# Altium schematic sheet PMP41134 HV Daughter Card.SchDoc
size 431 x 279 mm; PageSetup: Record=PageOptions¦CenterHorizontal=True¦CenterVertical=True¦PrintScale=1.00¦XCorrection=1.00¦YCorrection=1.00¦PrintKind=0¦BorderSize=5000000¦LeftOffset=0¦BottomOffset=0¦Orientation=2¦PaperLength=1000¦PaperWidth=1000¦Scale=100¦PaperSource=15¦PrintQuality=600¦MediaType=1¦DitherType=10¦PaperKind=Letter¦PrintScaleMode=1
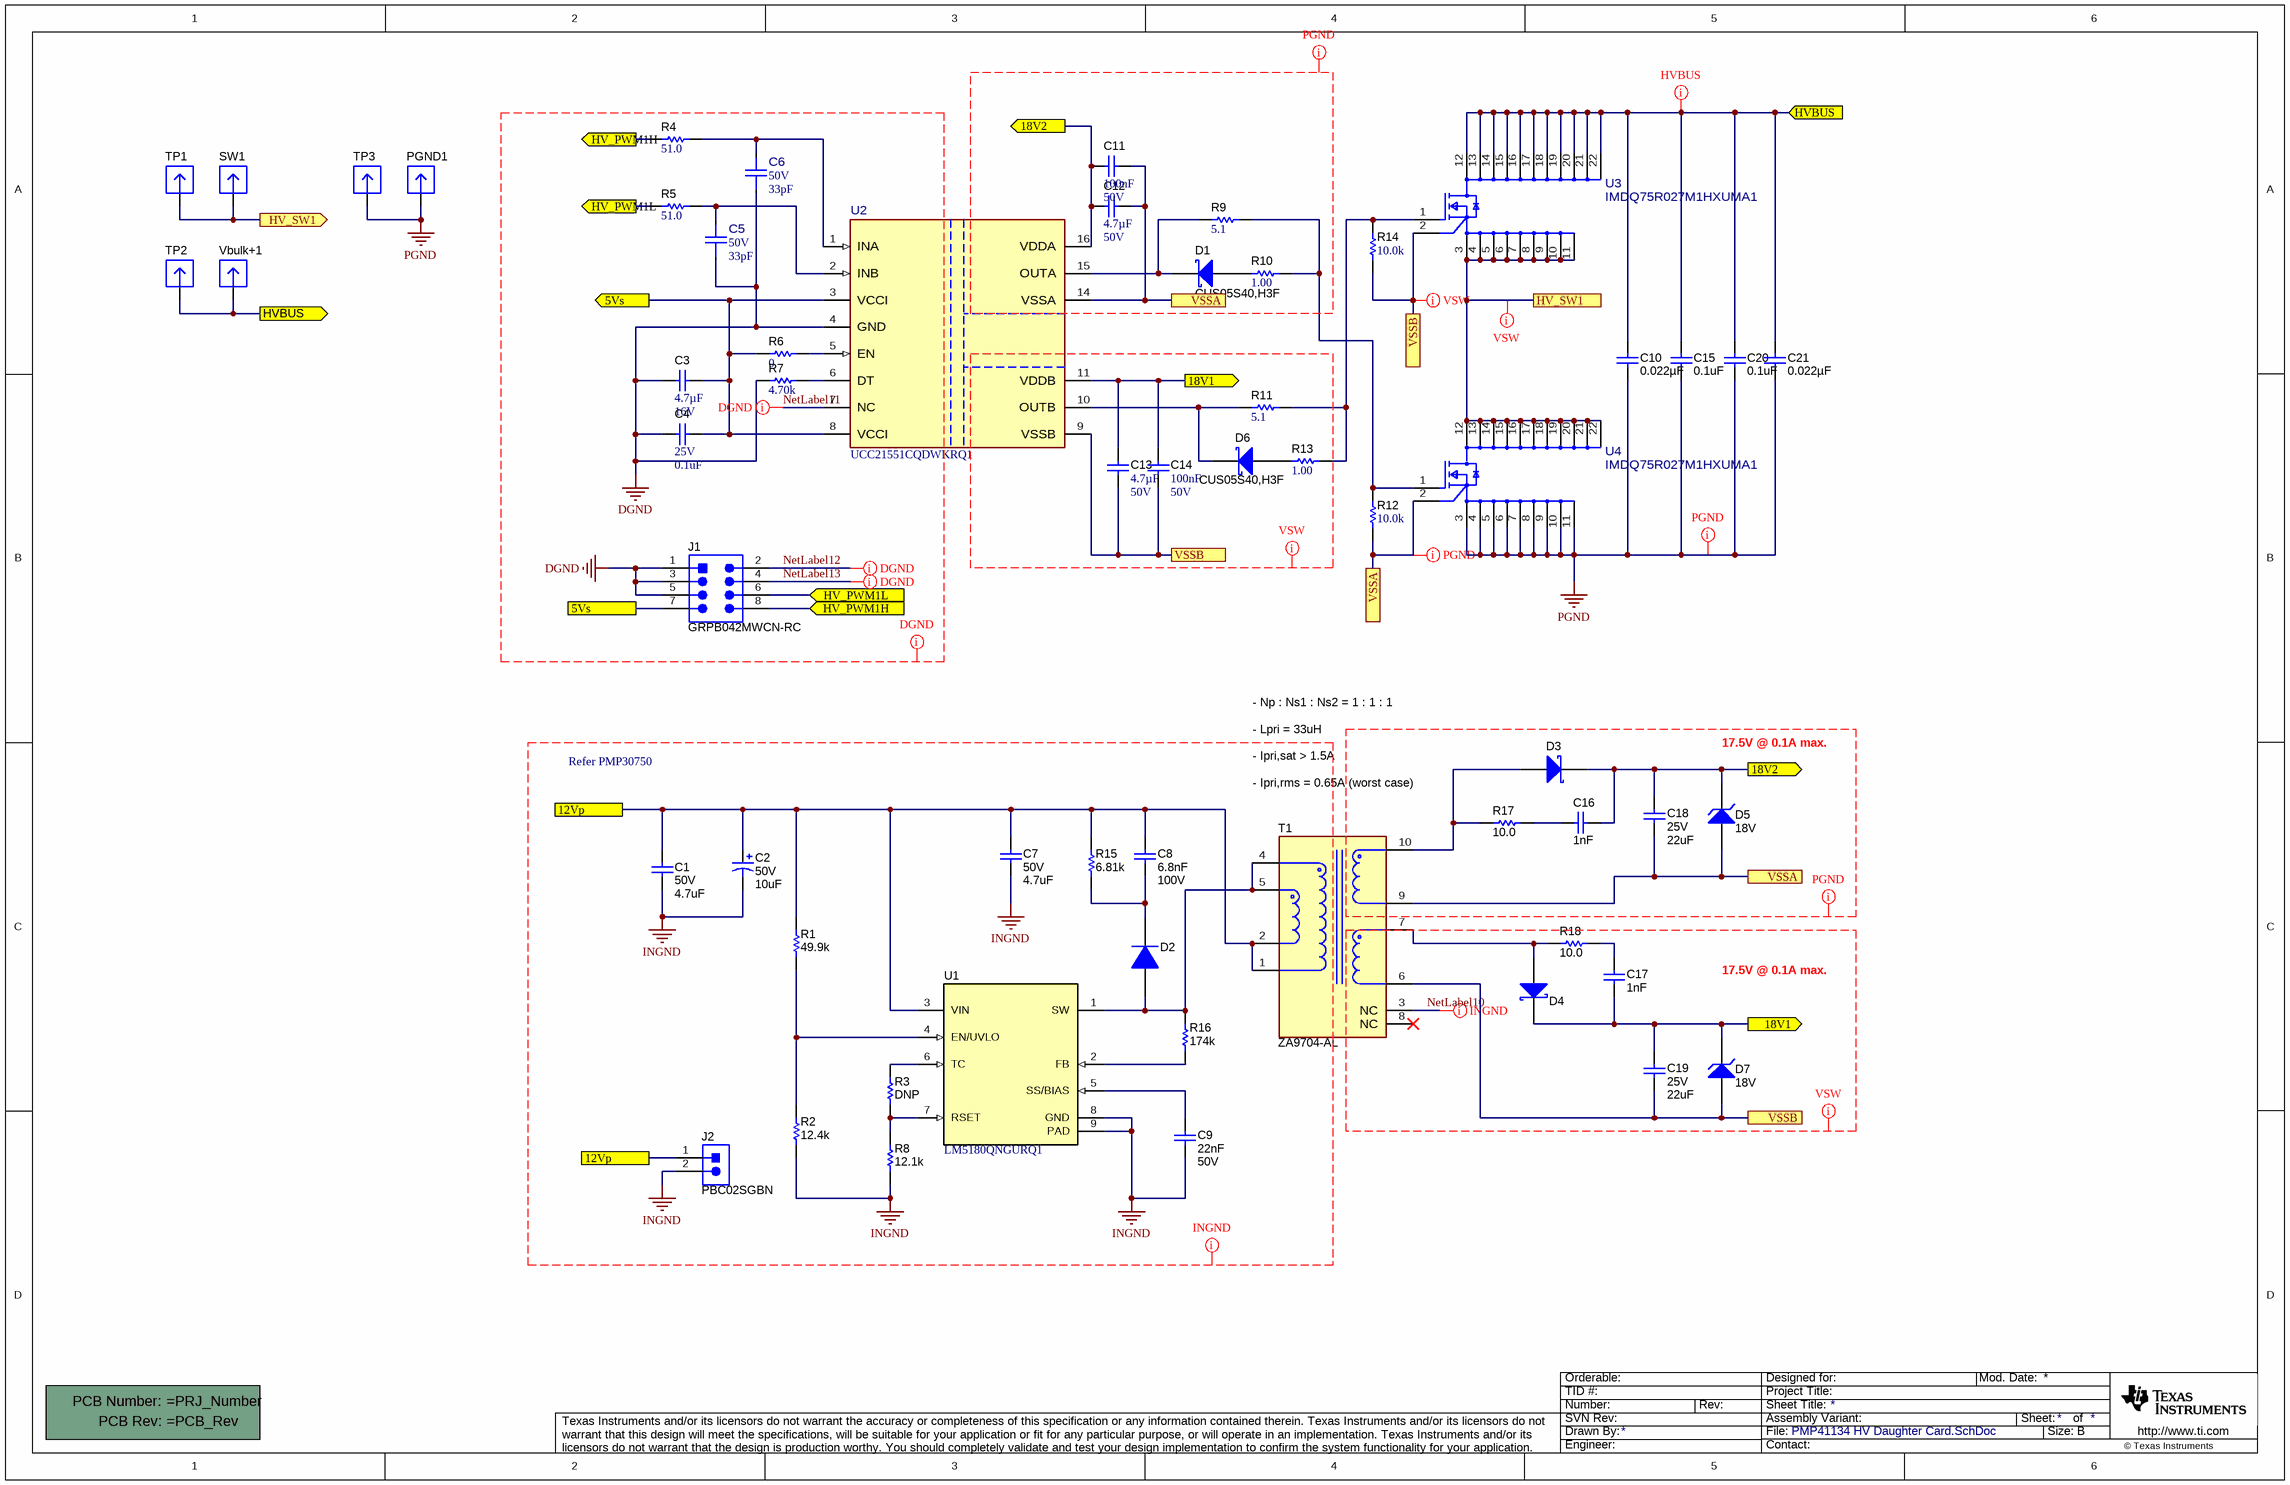
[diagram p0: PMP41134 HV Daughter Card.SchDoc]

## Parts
!PCB1  Printed Circuit Board  (value not drawn)  (mechanical)
C1  VDC_V: 50V  ValueDisplayed: 4.7uF  [1206_180]  (hidden comment: GRM31CR71H475KA12L)
C2  VDC_V: 50V  ValueDisplayed: 10uF  [SM_RADIAL_D]  (hidden comment: EEE-FK1H100P)
C3  Cap_F: 4.7µF  VDC_V: 16V  [0603]  (hidden comment: GRM188Z71C475KE21D)
C4  VDC_V: 25V  ValueDisplayed: 0.1uF  [0402]  (hidden comment: GRM155R71E104KE14D)
C5  VDC_V: 50V  ValueDisplayed: 33pF  [FP-CGA3E2C0G1H330J080AA_0603-MFG]  (hidden comment: CGA3E2C0G1H330J080AA)
C6  VDC_V: 50V  ValueDisplayed: 33pF  [FP-CGA3E2C0G1H330J080AA_0603-MFG]  (hidden comment: CGA3E2C0G1H330J080AA)
C7  VDC_V: 50V  ValueDisplayed: 4.7uF  [1206_180]  (hidden comment: GRM31CR71H475KA12L)
C8  Cap_F: 6.8nF  VDC_V: 100V  [0603]  (hidden comment: GRM188R72A682KA01D)
C9  Cap_F: 22nF  VDC_V: 50V  [0603]  (hidden comment: GRM188R71H223KA01D)
C10  ValueDisplayed: 0.022µF  [1206_190]  (hidden comment: C1206C223KDRACTU)
C11  Cap_F: 100nF  VDC_V: 50V  [0603]  (hidden comment: 885012206095)
C12  ValueDisplayed: 4.7µF  VDC_V: 50V  [1206_190]  (hidden comment: CGA5L3X7R1H475K160AE)
C13  ValueDisplayed: 4.7µF  VDC_V: 50V  [1206_190]  (hidden comment: CGA5L3X7R1H475K160AE)
C14  Cap_F: 100nF  VDC_V: 50V  [0603]  (hidden comment: 885012206095)
C15  ValueDisplayed: 0.1uF  [1812_254]  (hidden comment: C1812W104KDRACTU)
C16  Cap_F: 1nF  [0603]  (hidden comment: GRM188R71H102KA01D)
C17  Cap_F: 1nF  [0603]  (hidden comment: GRM188R71H102KA01D)
C18  VDC_V: 25V  ValueDisplayed: 22uF  [1210_270]  (hidden comment: TMK325B7226MM-PR)
C19  VDC_V: 25V  ValueDisplayed: 22uF  [1210_270]  (hidden comment: TMK325B7226MM-PR)
C20  ValueDisplayed: 0.1uF  [1812_254]  (hidden comment: C1812W104KDRACTU)
C21  ValueDisplayed: 0.022µF  [1206_190]  (hidden comment: C1206C223KDRACTU)
D1  CUS05S40,H3F  [SOD-323]
D2  BAS16D-E3-08  [SOD-123]  (value not drawn)
D3  PMEG6010CEH,115  [SOD-123]  (value not drawn)
D4  PMEG6010CEH,115  [SOD-123]  (value not drawn)
D5  value 18V  [SOD-123]  (hidden comment: MMSZ5248B-7-F)
D6  CUS05S40,H3F  [SOD-323]
D7  value 18V  [SOD-123]  (hidden comment: MMSZ5248B-7-F)
J1  GRPB042MWCN-RC  [Sullins_GRPB042MWCN]
J2  PBC02SGBN  [Sullins_PxC02SGBN]
PGND1  3621-0-32-15-00-00-08-0  [Mill-Max_3621-0-32-xx-00-00-08-0]  (value not drawn)
R1  ValueDisplayed: 49.9k  [0603]  (hidden comment: CRCW060349K9FKEA)
R2  ValueDisplayed: 12.4k  [0603]  (hidden comment: CRCW060312K4FKEA)
R3  ValueDisplayed: DNP  [0603]  (hidden comment: CRCW0603432KFKEA)
R4  ValueDisplayed: 51.0  [0603]  (hidden comment: RC0603FR-0751RL)
R5  ValueDisplayed: 51.0  [0603]  (hidden comment: RC0603FR-0751RL)
R6  ValueDisplayed: 0  [0402]  (hidden comment: RC0402JR-070RL)
R7  ValueDisplayed: 4.70k  [0402]  (hidden comment: CRG0402F4K7)
R8  ValueDisplayed: 12.1k  [0603]  (hidden comment: CRCW060312K1FKEA)
R9  ValueDisplayed: 5.1  [0603]  (hidden comment: CRCW06035R10JNEA)
R10  ValueDisplayed: 1.00  [0603]  (hidden comment: RC0603FR-071RL)
R11  ValueDisplayed: 5.1  [0603]  (hidden comment: CRCW06035R10JNEA)
R12  ValueDisplayed: 10.0k  [0402]  (hidden comment: ERJ-2RKF1002X)
R13  ValueDisplayed: 1.00  [0603]  (hidden comment: RC0603FR-071RL)
R14  ValueDisplayed: 10.0k  [0402]  (hidden comment: ERJ-2RKF1002X)
R15  ValueDisplayed: 6.81k  [0603]  (hidden comment: CRCW06036K81FKEA)
R16  ValueDisplayed: 174k  [0603]  (hidden comment: CRCW0603174KFKEA)
R17  ValueDisplayed: 10.0  [0603]  (hidden comment: CRCW060310R0FKEAHP)
R18  ValueDisplayed: 10.0  [0603]  (hidden comment: CRCW060310R0FKEAHP)
SW1  3621-0-32-15-00-00-08-0  [Mill-Max_3621-0-32-xx-00-00-08-0]  (value not drawn)
T1  ZA9704-AL  [FP-ZA9704-AL_SMD10-MFG]
TP1  3621-0-32-15-00-00-08-0  [Mill-Max_3621-0-32-xx-00-00-08-0]  (value not drawn)
TP2  3621-0-32-15-00-00-08-0  [Mill-Max_3621-0-32-xx-00-00-08-0]  (value not drawn)
TP3  3621-0-32-15-00-00-08-0  [Mill-Max_3621-0-32-xx-00-00-08-0]  (value not drawn)
U1  LM5180QNGURQ1  [NGU0008C]
U2  UCC21551CQDWKRQ1  [DWK0014A-MFG]
U3  IMDQ75R027M1HXUMA1  [FP-IMDQ75R027M1HXUMA1_HDSOP22-MFG]
U4  IMDQ75R027M1HXUMA1  [FP-IMDQ75R027M1HXUMA1_HDSOP22-MFG]
Vbulk+1  3621-0-32-15-00-00-08-0  [Mill-Max_3621-0-32-xx-00-00-08-0]  (value not drawn)

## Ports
5Vs, 5Vs (out), 12Vp, 18V1 (out), 18V2 (out), HV_PWM1H (in), HV_PWM1H (out), HV_PWM1L (in), HV_PWM1L (out), HV_SW1, HV_SW1 (out), HVBUS (in), HVBUS (out), VSSA, VSSB

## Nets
DGND: C3.1 C4.2 C5.1 C6.1 J1.1 J1.3 J1.5 R7.2 U2.4(GND)
INGND: C1.2 C2.2(-) C7.2 C9.2 J2.2 R2.1 R8.1 U1.8(GND) U1.9(PAD)
PGND: C10.2 C15.2 C20.2 C21.2 PGND1.1 TP3.1 U4.3(Power_Source) U4.4(Power_Source) U4.5(Power_Source) U4.6(Power_Source) U4.7(Power_Source) U4.8(Power_Source) U4.9(Power_Source) U4.10(Power_Source) U4.11(Power_Source)
5Vs: C3.2 C4.1 J1.7 R6.1 U2.3(VCCI) U2.8(VCCI) ; port 5Vs
12Vp: C1.1 C2.1(+) C7.1 C8.1 J2.1 R1.2 R15.2 T1.1 T1.2 U1.3(VIN) ; port 12Vp
18V1: C13.1 C14.1 C17.2 C19.1 D4.1(K) D7.1(K) U2.11(VDDB) ; port 18V1
18V2: C11.1 C12.1 C16.1 C18.1 D3.1(K) D5.1(K) U2.16(VDDA) ; port 18V2
HV_PWM1H: J1.8 R4.1 ; port HV_PWM1H
HV_PWM1L: J1.6 R5.1 ; port HV_PWM1L
HV_SW1: SW1.1 TP1.1 U3.3(Power_Source) U3.4(Power_Source) U3.5(Power_Source) U3.6(Power_Source) U3.7(Power_Source) U3.8(Power_Source) U3.9(Power_Source) U3.10(Power_Source) U3.11(Power_Source) U4.12(Drain) U4.13(Drain) U4.14(Drain) U4.15(Drain) U4.16(Drain) U4.17(Drain) U4.18(Drain) U4.19(Drain) U4.20(Drain) U4.21(Drain) U4.22(Drain) ; port HV_SW1
HVBUS: C10.1 C15.1 C20.1 C21.1 TP2.1 U3.12(Drain) U3.13(Drain) U3.14(Drain) U3.15(Drain) U3.16(Drain) U3.17(Drain) U3.18(Drain) U3.19(Drain) U3.20(Drain) U3.21(Drain) U3.22(Drain) Vbulk+1.1 ; port HVBUS
NetLabel10: T1.3(NC)
NetLabel11: U2.7(NC)
NetLabel12: J1.2
NetLabel13: J1.4
VSSA: C11.2 C12.2 C18.2 D5.2(A) R12.1 T1.9 U2.14(VSSA) U4.2(Driver_Source) ; port VSSA
VSSB: C13.2 C14.2 C19.2 D7.2(A) R14.1 T1.6 U2.9(VSSB) U3.2(Driver_Source) ; port VSSB
NetC5_2: C5.2 R5.2 U2.2(INB)
NetC6_2: C6.2 R4.2 U2.1(INA)
NetC8_2: C8.2 D2.1(K) R15.1
NetC9_1: C9.1 U1.5(SS/BIAS)
NetC16_2: C16.2 R17.2
NetC17_1: C17.1 R18.2
NetD1_1: D1.1(K) R9.1 U2.15(OUTA)
NetD1_2: D1.2(A) R10.1
NetD2_2: D2.2(A) R16.2 T1.4 T1.5 U1.1(SW)
NetD3_2: D3.2(A) R17.1 T1.10
NetD4_2: D4.2(A) R18.1 T1.7
NetD6_1: D6.1(K) R11.1 U2.10(OUTB)
NetD6_2: D6.2(A) R13.1
NetR1_1: R1.1 R2.2 U1.4(EN/UVLO)
NetR3_1: R3.1 R8.2 U1.7(RSET)
NetR3_2: R3.2 U1.6(TC)
NetR6_2: R6.2 U2.5(EN)
NetR7_1: R7.1 U2.6(DT)
NetR9_2: R9.2 R10.2 R12.2 U4.1(Gate)
NetR11_2: R11.2 R13.2 R14.2 U3.1(Gate)
NetR16_1: R16.1 U1.2(FB)

Not connected (* = marked no-connect by the designer): T1 8(NC)*

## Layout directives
net class INGND: INGND, NetLabel10
net class HVBUS: HVBUS
net class PGND: (no net found under the mark), PGND, VSSA
net class VSW: (no net found under the mark), HV_SW1, NetLabel10, VSSB
net class DGND: DGND, NetLabel11, NetLabel12, NetLabel13

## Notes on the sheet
- - Np : Ns1 : Ns2 = 1 : 1 : 1
- Refer PMP30750
- - Lpri = 33uH
- - Ipri,sat > 1.5A
- 17.5V @ 0.1A max.
- - Ipri,rms = 0.65A (worst case)

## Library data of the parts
!PCB1 = CMP-0003618-2: Manufacturer: Any
C1 C7 = CMP-0008969-2: CAP, CERM, 4.7 uF, 50 V, +/- 10%, X7R, 1206; Manufacturer: MuRata; TaMin_C: -55°C; Polarized: N; SizeAreaWB_mm2: 10.92; Value1: Unknown; U/M: EA; Value: 4.7uF; TaMax_C: 125°C; SizeZ_mm: 1.8; SizeX_mm: 3.2; SizeY_mm: 1.6; Cap_Case: 2220; SizeArea_mm2: 5.12; Cap_F: 4.7µF; AEC Category: Q200
C2 = CMP-0011175-2: CAP, AL, 10 uF, 50 V, +/- 20%, 0.88 ohm, AEC-Q200 Grade 2, SMD; Manufacturer: Panasonic; TaMin_C: -55°C; ESR_ohm: 0.88; Polarized: Y; SizeAreaWB_mm2: 84.28; U/M: EA; Value: 10uF; TaMax_C: 105°C; SizeZ_mm: 5.4; SizeX_mm: 7.8; SizeY_mm: 6.6; Cap_Case: D; SizeArea_mm2: 51.48; CompType: Capacitor; Cap_F: 10µF; IRMS_A: 165mA; AEC Grade: 2; AEC Category: Q200
C3 = CMP-0064936-4: CAP, CERM, 4.7 uF, 16 V,+/- 10%, X7R, 0603; Manufacturer: MuRata; TaMin_C: -55°C; Polarized: N; SizeAreaWB_mm2: 4.68; Value1: Unknown; U/M: EA; Value: 4.7uF; TaMax_C: 125°C; SizeZ_mm: 1; SizeX_mm: 1.6; SizeY_mm: 0.8; SizeArea_mm2: 1.28; AEC Category: Q200
C4 = CMP-0006659-2: CAP, CERM, 0.1 uF, 25 V, +/- 10%, X7R, 0402; Manufacturer: MuRata; TaMin_C: -55°C; Polarized: N; SizeAreaWB_mm2: 3; Value1: Unknown; U/M: EA; Value: 0.1uF; TaMax_C: 125°C; SizeZ_mm: 0.6; SizeX_mm: 1; SizeY_mm: 0.5; Cap_F: 100nF; AEC Category: Q200
C5 C6 = CMP-0095622-1: Cap Ceramic 33pF 50V C0G 5% Pad SMD 0603 +125°C Automotive T/R; Manufacturer: TDK; SizeZ_mm: 1.1mm; AEC Grade: Grade 1; Tolerance_%: 0.05%; AEC Qualified: Yes; TempCo: 30ppm/°C
C8 = CMP-0007487-4: CAP, CERM, 6800 pF, 100 V, +/- 10%, X7R, 0603; Manufacturer: MuRata; TaMin_C: -55°C; Polarized: N; SizeAreaWB_mm2: 4.68; Value1: Unknown; U/M: EA; Value: 6800pF; TaMax_C: 125°C; SizeZ_mm: 1; SizeX_mm: 1.6; SizeY_mm: 0.8; SizeArea_mm2: 1.28; AEC Category: Q200
C9 = CMP-0007444-4: CAP, CERM, 0.022 uF, 50 V, +/- 10%, X7R, 0603; Manufacturer: MuRata; TaMin_C: -55°C; Polarized: N; SizeAreaWB_mm2: 4.68; Value1: Unknown; U/M: EA; TaMax_C: 125°C; SizeZ_mm: 1; SizeX_mm: 1.6; SizeY_mm: 0.8; SizeArea_mm2: 1.28; AEC Category: Q200
C10 C21 = CMP-0084048-1: CAP, CERM, 0.022 µF, 1000 V,+/- 10%, X7R, AEC-Q200 Grade 1, 1206; Manufacturer: Kemet; Polarized: N; CompType: Capacitor; Value: 0.022uF; U/M: EA; Cap_F: 22nF; VDC_V: 1kV; Value2: 1000V; TaMin_C: -55°C; TaMax_C: 125°C; Cap_Case: 1206; SizeArea_mm2: 5.12; SizeAreaWB_mm2: 10.92; SizeX_mm: 3.2; SizeY_mm: 1.6; SizeZ_mm: 1.9; AEC Category: Q200; AEC Qualified: Y; AEC Grade: 1
C11 C14 = CMP-0006837-4: CAP, CERM, 0.1 uF, 50 V, +/- 10%, X7R, 0603; Manufacturer: Wurth Elektronik; TaMin_C: -55°C; Polarized: N; SizeAreaWB_mm2: 4.68; Value1: Unknown; U/M: EA; Value: 0.1uF; TaMax_C: 125°C; SizeZ_mm: 1; SizeX_mm: 1.6; SizeY_mm: 0.8; SizeArea_mm2: 1.28; AEC Category: Q200
C12 C13 = CMP-0085349-1: CAP, CERM, 4.7 µF, 50 V,+/- 10%, X7R, AEC-Q200 Grade 1, 1206; Manufacturer: TDK; Cap_Case: 1206; AEC Category: Q200; SizeY_mm: 1.6; TaMin_C: -55°C; TaMax_C: 125°C; U/M: EA; AEC Qualified: Y; SizeAreaWB_mm2: 10.92; AEC Grade: 1; SizeZ_mm: 1.9; SizeArea_mm2: 5.12; Value: 4.7uF; Polarized: N; SizeX_mm: 3.2
C15 C20 = CMP-0009326-2: CAP, CERM, 0.1 uF, 1000 V, +/- 10%, X7R, 1812; Manufacturer: Kemet; Polarized: N; Value: 0.1uF; U/M: EA; Cap_F: 100nF; Value1: Unknown; VDC_V: 1kV; Value2: 1000V; TaMin_C: -55°C; TaMax_C: 125°C; Cap_Case: 1812; AEC Category: Q200; SizeArea_mm2: 14.4; SizeAreaWB_mm2: 23.1; SizeX_mm: 4.5; SizeY_mm: 3.2; SizeZ_mm: 2.54
C16 C17 = CMP-0007432-5: CAP, CERM, 1000 pF, 50 V, +/- 10%, X7R, 0603; Manufacturer: MuRata; TaMin_C: -55°C; Polarized: N; SizeAreaWB_mm2: 4.68; Value1: Unknown; U/M: EA; Value: 1000pF; TaMax_C: 125°C; SizeZ_mm: 1; SizeX_mm: 1.6; SizeY_mm: 0.8; Value2: 50V; SizeArea_mm2: 1.28; AEC Category: Q200
C18 C19 = CMP-0009255-2: CAP, CERM, 22 uF, 25 V, +/- 10%, X7R, AEC-Q200 Grade 1, 1210; Manufacturer: Taiyo Yuden; TaMin_C: -55°C; Polarized: N; SizeAreaWB_mm2: 14.7; Value1: Unknown; U/M: EA; Value: 22uF; TaMax_C: 125°C; SizeZ_mm: 2.7; SizeX_mm: 3.2; SizeY_mm: 2.5; Cap_Case: 1210; SizeArea_mm2: 8; AEC Qualified: Y; Cap_F: 22µF; AEC Grade: 1; AEC Category: Q200
D1 D6 = CMP-0028748-2: Diode, Schottky, 40 V, 0.5 A, SOD-323; Manufacturer: Toshiba; TJmax_C: 125°C; Value: 40V; SizeZ_mm: 1; Value1: 0.5A; Value2: 0.6V; Io_A: 500mA; AEC Qualified: N; SizeAreaWB_mm2: 8.695; SizeY_mm: 1.35; SizeArea_mm2: 3.645; SizeX_mm: 2.7; AEC Category: Q101; Vf_V: 600mV; Green_Lifecycle: Not Set; Green_REACh: Incomplete
D2 = CMP-0080761-1: Diode, Switching, 100 V, 0.25 A, AEC-Q101, SOD-123; Manufacturer: Vishay-Semiconductor; Io_A: 250mA; SizeAreaWB_mm2: 13.095; Vr_V: 100V; Value1: 0.25A; TJmax_C: 150°C; Value: 100V; SizeZ_mm: 1.35; SizeX_mm: 3.85; SizeY_mm: 1.7; Vf_V: 1.25V; SizeArea_mm2: 6.545; AEC Qualified: Y; AEC Category: Q101
D3 D4 = CMP-0028377-2: Diode, Schottky, 60 V, 1 A, SOD-123F; Manufacturer: Nexperia; Value1: 1A; Value2: 0.57V; TJmax_C: 150°C; Green_REACh: Incomplete; Vr_V: 60V; SizeY_mm: 1.6; Vf_V: 570mV; SizeArea_mm2: 5.6; AEC Category: Q101; SizeZ_mm: 1.1; SizeX_mm: 3.5; Value: 60V; Green_Lifecycle: Not Set; SizeAreaWB_mm2: 11.7
D5 D7 = CMP-0005755-1: Diode, Zener, 18 V, 500 mW, SOD-123; Manufacturer: Diodes Inc.; Power_W: 500mW; SizeAreaWB_mm2: 13.095; Value1: 0.5W; RJA_CperW: 350; U/M: EA; SizeZ_mm: 1.35; SizeX_mm: 3.85; SizeY_mm: 1.7; SizeArea_mm2: 6.545; AEC Category: Q101
J1 = CMP-0086278-1: Header, 1.27mm, 4x2, Gold, R/A, TH; Manufacturer: Sullins Connector Solutions; Current_A: 1A; Shrouded: N; Pitch_mm: 1.27; Voltage_V: 500V; Gender: Male; Row_Count: 2
J2 = CMP-0054714-1: Header, 2.54 mm, 2x1, Gold, R/A, TH; Manufacturer: Sullins Connector Solutions; CNHeader: FALSE; Current_A: 3A; Shrouded: N; Gender: Male; Voltage_V: 1.8kV; Row_Count: 1; Pitch_mm: 2.54; Cert_UL: Y
PGND1 SW1 TP1-TP3 Vbulk+1 = CMP-0082316-1: Manufacturer: Mill-Max; CompType: PCB Pin; ContactFinish: Gold; Gender: Male; Row_Count: 1
R1 = CMP-0022447-4: RES, 49.9 k, 1%, 0.1 W, AEC-Q200 Grade 0, 0603; Manufacturer: Vishay-Dale; Power_W: 100mW; TempCo: 100 ppm/C; Value_Code: 49k9; Value: 49.9k; EIA_Code: E96; SizeX_mm: 1.6; SizeY_mm: 0.8; SizeZ_mm: 1; Value2: 0.1W; SizeArea_mm2: 1.28; AEC Qualified: Y; VDC_V: 75V; AEC Category: Q200; AEC Grade: 0
R2 = CMP-0022031-4: RES, 12.4 k, 1%, 0.1 W, AEC-Q200 Grade 0, 0603; Manufacturer: Vishay-Dale; Power_W: 100mW; TempCo: 100 ppm/C; Value_Code: 12k4; Value: 12.4k; EIA_Code: E96; SizeX_mm: 1.6; SizeY_mm: 0.8; SizeZ_mm: 1; Value2: 0.1W; SizeArea_mm2: 1.28; AEC Qualified: Y; VDC_V: 75V; AEC Category: Q200; AEC Grade: 0
R3 = CMP-0022420-4: RES, 432 k, 1%, 0.1 W, AEC-Q200 Grade 0, 0603; Manufacturer: Vishay-Dale; Power_W: 100mW; TempCo: 100 ppm/C; Value_Code: 432k; Value: 432k; EIA_Code: E96; SizeX_mm: 1.6; SizeY_mm: 0.8; SizeZ_mm: 1; Value2: 0.1W; SizeArea_mm2: 1.28; AEC Qualified: Y; VDC_V: 75V; AEC Category: Q200; AEC Grade: 0
R4 R5 = CMP-0023169-5: RES, 51.0, 1%, 0.1 W, 0603; Manufacturer: Yageo; Power_W: 100mW; TempCo: 100 ppm/C; Value_Code: 51R0; Value: 51.0; Res_ohm: 51; SizeX_mm: 1.6; SizeY_mm: 0.8; SizeZ_mm: 1; Value2: 0.1W; SizeArea_mm2: 1.28; AEC Qualified: N; VDC_V: 75V; AEC Category: Q200; SizeAreaWB_mm2: 4.68
R6 = CMP-0027004-2: RES, 0, 5%, 0.063 W, 0402; Manufacturer: Yageo America; Power_W: 63mW; TempCo: 200 ppm/C; Value_Code: 0000; U/M: EA; Value: 0; EIA_Code: E24; SizeX_mm: 1; SizeY_mm: 0.5; SizeZ_mm: 0.6; Value2: 0.063W; VDC_V: 50V; AEC Category: Q200
R7 = CMP-0026631-1: RES, 4.70 k, 1%, 0.063 W, 0402; Manufacturer: TE Connectivity; Power_W: 63mW; TempCo: 100 ppm/C; Value_Code: 4k70; U/M: EA; Value: 4.70k; Res_ohm: 4.7k; SizeX_mm: 1; SizeY_mm: 0.5; SizeZ_mm: 0.6; Value2: 0.063W; AEC Qualified: N; AEC Category: Q200
R8 = CMP-0022030-4: RES, 12.1 k, 1%, 0.1 W, AEC-Q200 Grade 0, 0603; Manufacturer: Vishay-Dale; Power_W: 100mW; TempCo: 100 ppm/C; Value_Code: 12k1; Value: 12.1k; EIA_Code: E96; SizeX_mm: 1.6; SizeY_mm: 0.8; SizeZ_mm: 1; Value2: 0.1W; SizeArea_mm2: 1.28; AEC Qualified: Y; VDC_V: 75V; AEC Category: Q200; AEC Grade: 0
R9 R11 = CMP-0025834-4: RES, 5.1, 5%, 0.1 W, AEC-Q200 Grade 0, 0603; Manufacturer: Vishay-Dale; Power_W: 100mW; TempCo: 200 ppm/C; Value_Code: 5R10; Value: 5.1; EIA_Code: E24; SizeX_mm: 1.6; SizeY_mm: 0.8; SizeZ_mm: 1; Value2: 0.1W; SizeArea_mm2: 1.28; AEC Qualified: Y; VDC_V: 75V; AEC Category: Q200; AEC Grade: 0
R10 R13 = CMP-0022900-4: RES, 1.00, 1%, 0.1 W, 0603; Manufacturer: Yageo; Power_W: 100mW; TempCo: 200 ppm/C; Value_Code: 1R00; Value: 1.00; EIA_Code: E96; Res_ohm: 1; SizeX_mm: 1.6; SizeY_mm: 0.8; Value2: 0.1W; SizeArea_mm2: 1.28; AEC Qualified: N; VDC_V: 75V; AEC Category: Q200; SizeAreaWB_mm2: 4.68
R12 R14 = CMP-0026658-1: RES, 10.0 k, 1%, 0.1 W, 0402; Manufacturer: Panasonic; Power_W: 100mW; TempCo: 100 ppm/C; Value_Code: 10k0; U/M: EA; Value: 10.0k; EIA_Code: E96; Res_ohm: 10k; SizeX_mm: 1; SizeY_mm: 0.5; SizeZ_mm: 0.6; Value2: 0.1W; VDC_V: 50V; AEC Category: Q200
R15 = CMP-0022563-4: RES, 6.81 k, 1%, 0.1 W, AEC-Q200 Grade 0, 0603; Manufacturer: Vishay-Dale; Power_W: 100mW; TempCo: 100 ppm/C; Value_Code: 6k81; Value: 6.81k; EIA_Code: E96; SizeX_mm: 1.6; SizeY_mm: 0.8; SizeZ_mm: 1; Value2: 0.1W; SizeArea_mm2: 1.28; AEC Qualified: Y; VDC_V: 75V; AEC Category: Q200; AEC Grade: 0
R16 = CMP-0022085-4: RES, 174 k, 1%, 0.1 W, AEC-Q200 Grade 0, 0603; Manufacturer: Vishay-Dale; Power_W: 100mW; TempCo: 100 ppm/C; Value: 174k; EIA_Code: E96; SizeX_mm: 1.6; SizeY_mm: 0.8; SizeZ_mm: 1; Value2: 0.1W; SizeArea_mm2: 1.28; AEC Qualified: Y; VDC_V: 75V; AEC Category: Q200; AEC Grade: 0
R17 R18 = CMP-0022004-4: RES, 10.0, 1%, 0.25 W, AEC-Q200 Grade 0, 0603; Manufacturer: Vishay-Dale; Power_W: 250mW; TempCo: 100 ppm/C; Value_Code: 10R0; Value: 10.0; EIA_Code: E96; Res_ohm: 10; SizeX_mm: 1.6; SizeY_mm: 0.8; SizeZ_mm: 1; Value2: 0.25W; SizeArea_mm2: 1.28; AEC Qualified: Y; VDC_V: 75V; AEC Category: Q200; AEC Grade: 0
T1 = CMP-0086949-1: FLYBACK TRANSFORMER; Manufacturer: Coilcraft; SizeZ_mm: 6.5mm; Ind_H: 32µH; Ns1toNp: 1:1:1; AEC Qualified: No
U1 = CMP-0078633-2: 70-V PSR Flyback Converter With 100-V, 1.2-A Power Switch and Ultra-Low IQ, NGU0008C (WSON-8); Alternate PartNumber: LM5180QNGUTQ1; Alternate Manufacturer: Texas Instruments; SizeAreaWB_mm2: 25; SizeZ_mm: 0.8; SizeX_mm: 4; SizeArea_mm2: 16; CompType: IC; AEC Qualified: Y; AEC Category: Q200
U2 = CMP-0001435-2: Automotive 4-A, 6-A, Reinforced Isolation Dual-Channel Gate Driver; Manufacturer: Texas Instruments; SizeZ_mm: 2.65mm; AEC Qualified: Yes; AEC Grade: Grade 1; Fall Time: 8ns; Max Power Dissipation: 950mW; Max Supply Voltage: 25V; Min Supply Voltage: 3V; Number Of Drivers: 2; Propagation Delay: 33ns; Standoff Height: 0.1mm; TJmax_C: +150°C; AEC Category: Q200; CompType: IC
U3 U4 = CMP-0123083-1: N-Channel 750 V 64A (Tj) 273W (Tc) Surface Mount PG-HDSOP-22-1; Manufacturer: Infineon; AEC Qualified: No; QgTyp_nC: 49nC @ 18V; Rdson45_ohm: 27m; SizeZ_mm: 2.5mm; VdsMax_V: 5.3V; Vgs_V: 23V; ChMode: False; Input Capacitance At Vds: 1668pF @ 500V; Number Of Channels: 1; Pulse Drain Current: 198A; Reverse Recovery Charge: 164nC; Reverse Recovery Time: 13ns; Standoff Height: 0mm; Threshold Vgs Max: 5.6V; Threshold Vgs Min: 3.5V; TJmax_C: +175°C; Turn Off Delay Time: 24ns; Turn On Delay Time: 11ns; Typ Forward Diode Voltage: 3.9V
